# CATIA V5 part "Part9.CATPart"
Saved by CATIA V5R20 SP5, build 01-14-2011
Part number: Part9
Bounding box of the stored display mesh (mm): x -60 to 60, y -60 to 60, z 0 to 34
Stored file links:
  C:\Documents and Settings\Student\桌面\Part9.CATPart
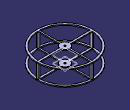
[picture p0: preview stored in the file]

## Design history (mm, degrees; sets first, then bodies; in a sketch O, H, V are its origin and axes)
Body1 (main body)
  Sketch1 on xy-plane, origin (0, 0, 0), H (1, 0, 0), V (0, 1, 0)
    circle A1 centre (0, 0) radius 2
    arc A2 centre (0, 0) radius 10 from (-9.7688, -2.1378) to (-1.4878, -9.8887) ccw
    circle A3 centre (0, 0) radius 60
    arc A4 centre (0, 0) radius 56 from (-1.4878, 55.9802) to (-55.9592, 2.1378) ccw
    line L1 (1.4878, 9.8887) -> (1.4878, 55.9802)
    line L2 (-1.4878, 9.8887) -> (-1.4878, 55.9802)
    point P3 (-1.4878, 9.8887)
    line L3 (1.4878, -9.8887) -> (1.4878, -55.9802)
    point P5 (1.4878, -9.8887)
    point P6 (1.4878, -55.9802)
    line L4 (-1.4878, -9.8887) -> (-1.4878, -55.9802)
    point P7 (-1.4878, -9.8887)
    point P8 (-1.4878, -55.9802)
    line L5 (9.7688, 2.1378) -> (55.9592, 2.1378)
    point P9 (9.7688, 2.1378)
    point P10 (55.9592, 2.1378)
    line L6 (9.7688, -2.1378) -> (55.9592, -2.1378)
    line L7 (-9.7688, 2.1378) -> (-55.9592, 2.1378)
    point P13 (-9.7688, 2.1378)
    line L8 (-9.7688, -2.1378) -> (-55.9592, -2.1378)
    point P15 (-9.7688, -2.1378)
    point P16 (-55.9592, -2.1378)
    arc A5 centre (0, 0) radius 10 from (-1.4878, 9.8887) to (-9.7688, 2.1378) ccw
    arc A6 centre (0, 0) radius 10 from (9.7688, 2.1378) to (1.4878, 9.8887) ccw
    arc A7 centre (0, 0) radius 10 from (1.4878, -9.8887) to (9.7688, -2.1378) ccw
    arc A8 centre (0, 0) radius 56 from (55.9592, 2.1378) to (1.4878, 55.9802) ccw
    arc A9 centre (0, 0) radius 56 from (-55.9592, -2.1378) to (-1.4878, -55.9802) ccw
    arc A10 centre (0, 0) radius 56 from (1.4878, -55.9802) to (55.9592, -2.1378) ccw
    vertical: L1 V, L2 V, L3 V, L4 V
    coincidence: P3 A2, P5 L1, P5 A2, P6 A4, P7 L2, P8 A4, P9 A2, P10 A4, P13 L5, P15 L6, P16 A4, A2 A5, A2 A6, A2 A7, A4 A8, A4 A9, A9 A10
    horizontal: L5 H, L6 H, L7 H, L8 H
  Pad1: profile Sketch1, direction (0, 0, 1), length 2
  Plane1: type Offset, RefPlane xy-plane, Offset 2
  Sketch2 on Plane1, origin (0, 0, 2), H (1, 0, 0), V (0, 1, 0)
    line L1 (56.0893, 2.2061) -> (59.1351, 2.2061)
    line L2 (59.1351, 2.2061) -> (59.1351, -2.0956)
    line L3 (59.1351, -2.0956) -> (56.0893, -2.0956)
    line L4 (56.0893, -2.0956) -> (56.0893, 2.2061)
    horizontal: L1 H, L3 H
    vertical: L2 V, L4 V
  Pad2: profile Sketch2, direction (0, 0, 1), length 30
  CircPattern1: of Pad2, instances 4, angular step 90, axis from end face of Pad1
  Plane2: type Offset, RefPlane Plane1, Offset 15
  Mirror1: of the body so far, about Plane2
